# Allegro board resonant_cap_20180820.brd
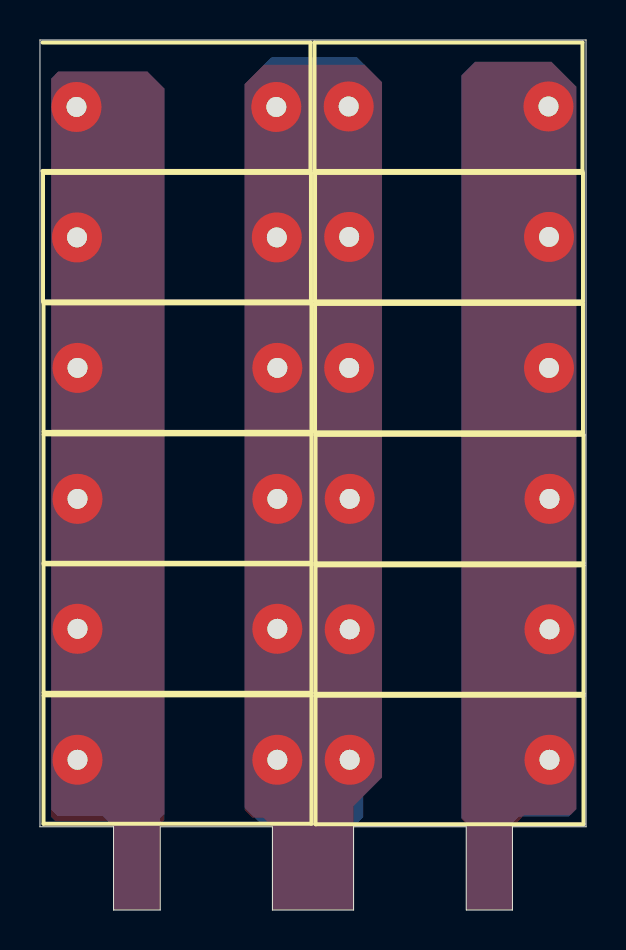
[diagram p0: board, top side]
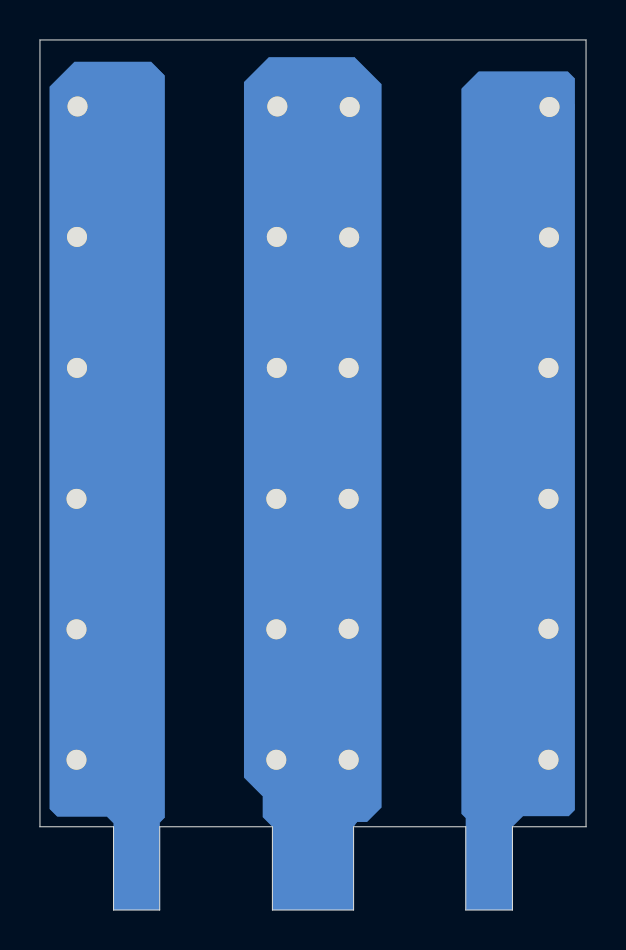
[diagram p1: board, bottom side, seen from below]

Outline 27.33 x 43.54 mm; copper layers: TOP, BOTTOM. Coordinates in mm from the lower left corner of the outline.
Outline path: 0,43.54 27.33,43.54 27.33,4.17 23.65,4.17 23.65,0 21.34,0 21.34,4.17 15.7,4.17 15.7,0 11.63,0 11.63,4.17 6.02,4.17 6.02,0 3.68,0 3.68,4.17 0,4.17 0,43.54

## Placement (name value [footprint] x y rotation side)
C1  6.8n  [B32651A7682J000]  1.88 27.13 0 top
C2  6.8n  [B32651A7682J000]  25.5 20.57 180 top
C3  6.8n  [B32651A7682J000]  1.88 7.52 0 top
C4  6.8n  [B32651A7682J000]  1.85 33.66 0 top
C5  6.8n  [B32651A7682J000]  25.48 33.68 180 top
C6  6.8n  [B32651A7682J000]  1.83 40.18 0 top
C7  6.8n  [B32651A7682J000]  1.88 14.07 0 top
C8  6.8n  [B32651A7682J000]  25.5 14.05 180 top
C9  6.8n  [B32651A7682J000]  25.5 7.52 180 top
C10  6.8n  [B32651A7682J000]  25.48 27.13 180 top
C11  6.8n  [B32651A7682J000]  25.45 40.21 180 top
C12  6.8n  [B32651A7682J000]  1.88 20.57 0 top

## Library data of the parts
C1-C12 = CAP NP

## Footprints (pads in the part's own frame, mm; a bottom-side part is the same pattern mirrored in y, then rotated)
B32651A7682J000
  round 2.5 hole 1: 1(0,0) 2(10,0)

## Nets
N00405: C1.1 C3.1 C4.1 C6.1 C7.1 C12.1
N00421: C1.2 C2.2 C3.2 C4.2 C5.2 C6.2 C7.2 C8.2 C9.2 C10.2 C11.2 C12.2
N00657: C2.1 C5.1 C8.1 C9.1 C10.1 C11.1

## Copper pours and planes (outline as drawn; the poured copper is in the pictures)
N00405 on BOTTOM (solid shape): 6.24,41.1 6.24,4.81 6.02,4.6 6.02,0 3.68,0 3.68,4.17 3.15,4.7 0.86,4.7 0.56,5 0.56,41.61 0.91,41.96 5.37,41.96
N00405 on TOP: 6.24,41.1 6.24,4.52 6.02,4.31 6.02,0 3.68,0 3.68,4.17 3.4,4.45 0.76,4.45 0.56,4.65 0.56,41.61 0.91,41.96 5.37,41.96
N00421 on BOTTOM (solid shape): 17.12,41.43 17.12,6.63 16.18,5.69 16.18,4.65 15.7,4.17 15.7,0 11.63,0 11.63,4.17 11.46,4.41 10.96,4.41 10.24,5.13 10.24,41.33 11.58,42.67 15.88,42.67
N00421 on TOP: 10.24,41.33 10.24,5 10.62,4.62 11.18,4.62 11.63,4.17 11.63,0 15.7,0 15.7,5.21 17.12,6.63 17.12,41.43 16.26,42.29 11.2,42.29
N00657 on BOTTOM (solid shape): 26.85,41.2 26.85,5.05 26.47,4.67 23.98,4.67 23.65,4.34 23.65,0 21.34,0 21.34,4.37 21.08,4.62 21.08,41.76 21.77,42.44 25.6,42.44
N00657 on TOP: 26.85,41.2 26.85,5.05 26.54,4.75 24.23,4.75 23.65,4.17 23.65,0 21.34,0 21.34,4.32 21.09,4.56 21.09,41.77 21.77,42.44 25.6,42.44
